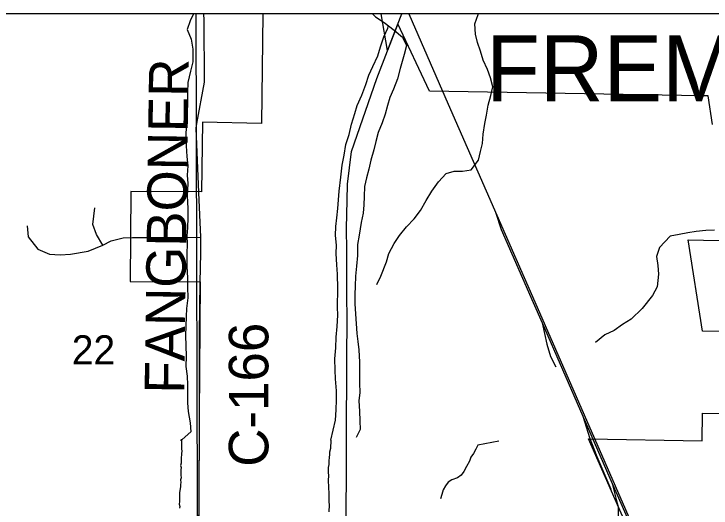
# Model space of a CAD drawing. Extents: x -8.5 to 18.7, y -20.3 to 7.
# Drawn here: x -6.189 to -4.185, y 5.518 to 6.938 of the extents above; entities that cross this region are included whole.
import ezdxf

# ---------------------------------------------------------------- set-up
doc = ezdxf.new("R2010")
doc.units = 0
for name, color, linetype in [('Default', 7, 'Continuous'), ('GM_X_City_Street', 7, 'Continuous'), ('GM_X_Corporation', 7, 'Continuous'), ('GM_X_Corporation_Text', 7, 'Continuous'), ('GM_X_County_Road', 7, 'Continuous'), ('GM_X_County_Road_Text', 7, 'Continuous'), ('GM_X_Minor_River', 7, 'Continuous'), ('GM_X_Rail_Line', 7, 'Continuous'), ('GM_X_Section_Text', 7, 'Continuous'), ('GM_X_State_Route', 7, 'Continuous'), ('GM_X_Township_Road', 7, 'Continuous'), ('SH_Cut_Line', 7, 'Continuous')]:
    doc.layers.add(name, color=color, linetype=linetype)

msp = doc.modelspace()

# ---------------------------------------------------------------- linework, layer by layer
at = {"layer": 'Default'}
msp.add_lwpolyline([(-5.6649, 6.938), (-6.2268, 6.938), (-6.2691, 5.158), (-5.6605, 5.1719)], close=True, dxfattribs=at)
at = {"layer": 'GM_X_City_Street'}
for points in [[(-4.1809, 6.6201), (-4.194, 6.7024), (-4.2144, 6.7028), (-4.9947, 6.7162), (-5.0857, 6.9092), (-5.1153, 6.8331), (-5.1332, 6.938), (-5.474, 6.938), (-5.4779, 6.6229), (-5.6471, 6.6268), (-5.6502, 6.4267), (-5.8532, 6.428), (-5.8546, 6.1696), (-5.6538, 6.1683), (-5.657, 5.7842), (-5.6572, 5.529), (-5.66, 5.41), (-5.6767, 4.8185), (-5.6804, 4.6863), (-6.0625, 4.6973), (-6.0668, 4.6758), (-6.5241, 4.6888)], [(-4.1528, 6.0255), (-4.2096, 6.0265), (-4.2512, 6.2886), (-4.1182, 6.2863)], [(-4.7717, 4.2426), (-4.7696, 4.5473), (-4.3639, 4.5333), (-4.3263, 4.5938), (-4.4059, 4.6121), (-4.618, 4.6571), (-4.6937, 4.6584), (-4.769, 4.6325), (-4.769, 4.7663), (-4.8156, 4.8617), (-4.7678, 4.8625), (-4.7725, 5.0989), (-4.31, 5.0918), (-4.4074, 5.4029), (-4.439, 5.4772), (-4.4331, 5.4798), (-4.5376, 5.7173), (-4.2111, 5.7117), (-4.2097, 5.7905), (-4.0623, 5.788)]]:
    msp.add_lwpolyline(points, dxfattribs=at)
at = {"layer": 'GM_X_Corporation'}
msp.add_lwpolyline([(-0.1911, 6.938), (-8.4587, 6.938), (-8.4587, 1.1732)], dxfattribs=at)
at = {"layer": 'GM_X_County_Road'}
msp.add_line((-5.6534, 6.1671), (-5.6522, 6.2508), dxfattribs=at)
for points in [[(-5.6632, 6.6231), (-5.6415, 6.7415), (-5.642, 6.9199), (-5.6428, 6.938)], [(-5.6574, 6.4253), (-5.6657, 6.6093), (-5.6632, 6.6231)], [(-5.6522, 6.2508), (-5.6516, 6.2967), (-5.6574, 6.4253)], [(-5.6571, 5.4361), (-5.6567, 5.5279), (-5.6563, 5.6345), (-5.6561, 5.6739), (-5.6559, 5.7831), (-5.6555, 6.0217), (-5.6534, 6.1671)]]:
    msp.add_lwpolyline(points, dxfattribs=at)
at = {"layer": 'GM_X_Minor_River'}
for points in [[(-5.6732, 6.938), (-5.6829, 6.9178), (-5.6907, 6.8928), (-5.6795, 6.8654), (-5.6744, 6.8364), (-5.6747, 6.7999), (-5.6817, 6.7734), (-5.6895, 6.7408), (-5.6905, 6.7127), (-5.6899, 6.6823), (-5.6909, 6.6534), (-5.6934, 6.6253), (-5.6951, 6.5934), (-5.6939, 6.5592), (-5.6918, 6.5287), (-5.6897, 6.5014), (-5.6907, 6.4748), (-5.6893, 6.4504), (-5.6911, 6.4155), (-5.6891, 6.379), (-5.6893, 6.3531), (-5.6902, 6.3235), (-5.6919, 6.3), (-5.6913, 6.2764), (-5.6923, 6.2498), (-5.6918, 6.2126), (-5.6898, 6.1799), (-5.69, 6.1533), (-5.6894, 6.1221), (-5.6927, 6.0917), (-5.6936, 6.0682), (-5.6946, 6.0408), (-5.6963, 6.0135), (-5.695, 5.9846), (-5.6944, 5.9549), (-5.6947, 5.9253), (-5.6911, 5.8971), (-5.6905, 5.872), (-5.6899, 5.8447), (-5.6901, 5.8203), (-5.688, 5.7952), (-5.6829, 5.7633), (-5.6808, 5.7367), (-5.7057, 5.7154)], [(-5.1587, 6.938), (-5.1494, 6.9301), (-5.1253, 6.9132), (-5.0966, 6.8909), (-5.0725, 6.871), (-5.0605, 6.8473), (-5.0675, 6.8215), (-5.0792, 6.7813), (-5.087, 6.7517), (-5.0978, 6.7222), (-5.1086, 6.698), (-5.1156, 6.6745), (-5.1219, 6.6502), (-5.1311, 6.6252), (-5.142, 6.5971), (-5.149, 6.5714), (-5.1545, 6.5478), (-5.163, 6.5175), (-5.1693, 6.4917), (-5.1755, 6.4675), (-5.181, 6.4417), (-5.182, 6.4135), (-5.1837, 6.3892), (-5.1854, 6.3657), (-5.1909, 6.3384), (-5.1965, 6.3027), (-5.2012, 6.2754), (-5.2014, 6.2435), (-5.2047, 6.2131), (-5.2072, 6.1842), (-5.2081, 6.1561), (-5.2091, 6.1318), (-5.2093, 6.1052), (-5.2072, 6.0763), (-5.2031, 6.02), (-5.201, 5.9964), (-5.1981, 5.9728), (-5.1961, 5.9371), (-5.1963, 5.909), (-5.1957, 5.8771), (-5.1952, 5.8504), (-5.1976, 5.8261), (-5.1963, 5.7965), (-5.195, 5.7684), (-5.1944, 5.744), (-5.2052, 5.7206)], [(-5.1459, 6.1609), (-5.1343, 6.1844), (-5.1181, 6.2253), (-5.1119, 6.2495), (-5.0965, 6.2783), (-5.0811, 6.3017), (-5.0612, 6.3259), (-5.0391, 6.3493), (-5.0207, 6.3734), (-5.0038, 6.4022), (-4.9877, 6.4287), (-4.9685, 6.4559), (-4.9471, 6.4792), (-4.9235, 6.4866), (-4.9, 6.4865), (-4.8749, 6.49), (-4.8542, 6.518), (-4.848, 6.5423), (-4.8425, 6.5658), (-4.8408, 6.5924), (-4.836, 6.6235), (-4.8305, 6.647), (-4.8258, 6.6759), (-4.8187, 6.7039), (-4.8125, 6.7289), (-4.8191, 6.7541), (-4.8281, 6.7785), (-4.84, 6.8052), (-4.8482, 6.8311), (-4.8563, 6.8562), (-4.8622, 6.8798), (-4.8643, 6.9095), (-4.855, 6.936), (-4.8536, 6.938)], [(-5.2784, 5.713), (-5.2648, 5.7705), (-5.2631, 5.8001), (-5.2621, 5.829), (-5.2619, 5.8548), (-5.2647, 5.8898), (-5.266, 5.9141), (-5.2666, 5.9468), (-5.2641, 5.9787), (-5.2631, 6.0091), (-5.2598, 6.0395), (-5.2581, 6.0721), (-5.2587, 6.0957), (-5.2583, 6.1489), (-5.2587, 6.19), (-5.2608, 6.2173), (-5.2629, 6.25), (-5.2619, 6.2736), (-5.2647, 6.3017), (-5.2638, 6.3276), (-5.2614, 6.3519), (-5.2581, 6.3792), (-5.254, 6.4286), (-5.2499, 6.4688), (-5.2458, 6.5038), (-5.2403, 6.5326), (-5.2348, 6.563), (-5.2255, 6.5918), (-5.2184, 6.6213), (-5.2091, 6.6517), (-5.2021, 6.6752), (-5.189, 6.7047), (-5.1774, 6.735), (-5.1689, 6.7623), (-5.158, 6.7873), (-5.1434, 6.8176), (-5.1356, 6.8434), (-5.1256, 6.8722), (-5.1148, 6.8971), (-5.1128, 6.9045)], [(-4.1759, 6.3163), (-4.2001, 6.3157), (-4.2282, 6.3129), (-4.2518, 6.3093), (-4.2769, 6.3042), (-4.3027, 6.2998), (-4.3333, 6.2666), (-4.3418, 6.2409), (-4.3382, 6.215), (-4.3361, 6.1899), (-4.3402, 6.1535), (-4.354, 6.1292), (-4.3839, 6.0915), (-4.4152, 6.0613), (-4.4396, 6.0456), (-4.464, 6.0283), (-4.4906, 6.0156), (-4.5173, 5.9938)], [(-5.7087, 5.711), (-5.7071, 5.7159), (-5.7076, 5.6943), (-5.7077, 5.6882), (-5.7063, 5.6814), (-5.7072, 5.6753), (-5.7073, 5.67), (-5.7082, 5.6647), (-5.7086, 5.6473), (-5.7102, 5.6405), (-5.7088, 5.6344), (-5.7097, 5.6276), (-5.7091, 5.62), (-5.7093, 5.6124), (-5.7087, 5.6048), (-5.7103, 5.5995), (-5.7097, 5.5912), (-5.7106, 5.5859), (-5.7107, 5.5798), (-5.7134, 5.5616), (-5.7136, 5.5488), (-5.713, 5.5427), (-5.7131, 5.5366), (-5.714, 5.529), (-5.7119, 5.5229), (-5.7135, 5.5176)], [(-5.2779, 5.7133), (-5.2791, 5.6896), (-5.2816, 5.679), (-5.2825, 5.6722), (-5.2827, 5.6631), (-5.2836, 5.654), (-5.2839, 5.6434), (-5.2863, 5.6343), (-5.2857, 5.626), (-5.2859, 5.6191), (-5.2852, 5.6131), (-5.2856, 5.5964), (-5.2857, 5.5911), (-5.2851, 5.5835), (-5.2853, 5.5751), (-5.284, 5.5615), (-5.2842, 5.5539), (-5.2836, 5.5478), (-5.2838, 5.5364), (-5.2832, 5.5273), (-5.2837, 5.5068)], [(-4.7954, 5.7103), (-4.856, 5.6991), (-4.8615, 5.6878), (-4.8685, 5.6749), (-4.8754, 5.6644), (-4.8801, 5.6531), (-4.8879, 5.638), (-4.8964, 5.6236), (-4.9033, 5.6123), (-4.914, 5.6048), (-4.93, 5.5997), (-4.9407, 5.5922), (-4.9484, 5.5817), (-4.9554, 5.5703), (-4.9593, 5.5567), (-4.9633, 5.5446)]]:
    msp.add_lwpolyline(points, dxfattribs=at)
at = {"layer": 'GM_X_Rail_Line'}
for points in [[(-5.0541, 6.938), (-4.9411, 6.6786), (-4.6924, 6.1108), (-4.4021, 5.4457)], [(-4.8053, 6.3686), (-4.7883, 6.3181), (-4.6967, 6.109), (-4.671, 6.05), (-4.5542, 5.7823), (-4.4695, 5.5883), (-4.4203, 5.4756), (-4.4064, 5.4439), (-4.3818, 5.3852), (-4.3519, 5.3073), (-4.3383, 5.2672), (-4.3202, 5.2116), (-4.3054, 5.1615), (-4.2882, 5.1155)], [(-4.671, 6.05), (-4.6573, 5.9889), (-4.647, 5.9538), (-4.6311, 5.9241)], [(-4.5542, 5.7823), (-4.5336, 5.7178), (-4.5136, 5.6665), (-4.4734, 5.5721)], [(-4.4695, 5.5883), (-4.4582, 5.543), (-4.4527, 5.522), (-4.4523, 5.4968), (-4.4516, 5.4192)]]:
    msp.add_lwpolyline(points, dxfattribs=at)
at = {"layer": 'GM_X_State_Route'}
msp.add_line((-5.0867, 6.9064), (-5.0746, 6.938), dxfattribs=at)
for points in [[(-5.1152, 6.8322), (-5.1064, 6.855), (-5.0867, 6.9064)], [(-5.2315, 6.4021), (-5.2305, 6.449), (-5.2186, 6.5425), (-5.1458, 6.7524), (-5.1152, 6.8322)], [(-5.2326, 6.2574), (-5.233, 6.3226), (-5.2315, 6.4021)], [(-5.2321, 5.9598), (-5.232, 5.9822), (-5.231, 6.0271), (-5.2319, 6.1637), (-5.2326, 6.2574)], [(-5.2412, 4.7216), (-5.2405, 4.745), (-5.2388, 4.8655), (-5.2367, 5.1491), (-5.2367, 5.1599), (-5.2337, 5.4315), (-5.2321, 5.9598)]]:
    msp.add_lwpolyline(points, dxfattribs=at)
at = {"layer": 'GM_X_Township_Road'}
for points in [[(-5.9332, 6.274), (-5.952, 6.3046), (-5.9619, 6.3332), (-5.9569, 6.3805)], [(-6.1512, 6.3292), (-6.1483, 6.2977), (-6.1207, 6.2621), (-6.0871, 6.2473), (-6.0565, 6.2454), (-6.026, 6.2473), (-5.9757, 6.2562), (-5.9332, 6.274), (-5.9096, 6.2858), (-5.875, 6.2947), (-5.8486, 6.2954)], [(-5.8486, 6.2954), (-5.8405, 6.2957), (-5.8001, 6.2957), (-5.7803, 6.2957)], [(-5.7803, 6.2957), (-5.733, 6.2957), (-5.6516, 6.2967)]]:
    msp.add_lwpolyline(points, dxfattribs=at)
at = {"layer": 'SH_Cut_Line'}
msp.add_lwpolyline([(18.7413, 6.938), (-8.4587, 6.938), (-8.4587, -10.6981)], dxfattribs=at)

# ---------------------------------------------------------------- texts
at = {"layer": 'GM_X_Corporation_Text'}
msp.add_text('FREMONT', height=0.18939, rotation=0, dxfattribs=at).set_placement((-4.8322, 6.6871))
at = {"layer": 'GM_X_County_Road_Text'}
for s, rotation, p in [('FANGBONER', 89.2122, (-5.6999, 5.8464)), ('C-166', 90, (-5.4577, 5.6368))]:
    msp.add_text(s, height=0.11364, rotation=rotation, dxfattribs=at).set_placement(p)
at = {"layer": 'GM_X_Section_Text'}
msp.add_text('22', height=0.08371, rotation=0, dxfattribs=at).set_placement((-6.0227, 5.9309))

doc.saveas('drawing.dxf')
